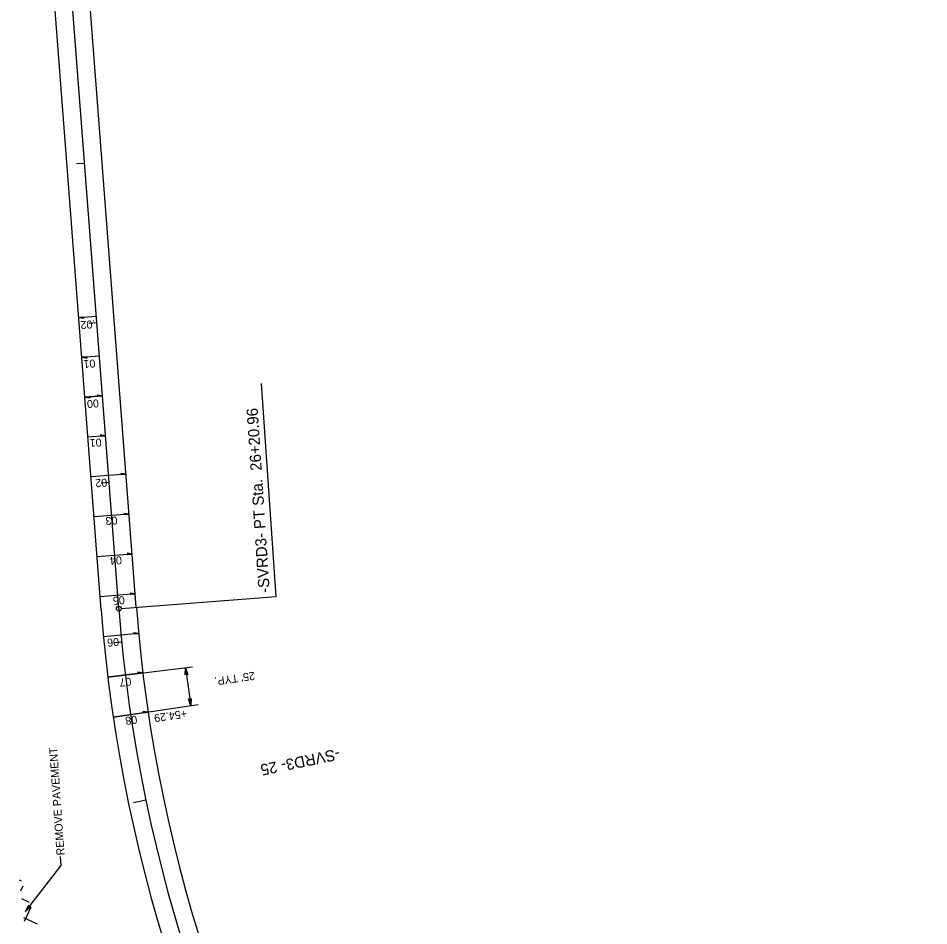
# Model space of a CAD drawing. Extents: x 2389694 to 2405615, y 547005 to 573532.
# Drawn here: x 2400508 to 2401078, y 564597 to 565164 of the extents above; entities that cross this region are included whole.
import ezdxf

# ---------------------------------------------------------------- set-up
doc = ezdxf.new("R2010")
doc.units = 0
for name, color, linetype in [('Prop Dimension', 7, 'Continuous'), ('Prop Dimension Text', 7, 'Continuous'), ('Prop EOT', 7, 'Continuous'), ('Prop Hatching', 7, 'Continuous'), ('Prop Horizontal Alignment', 7, 'Continuous'), ('Prop Horizontal Alignment Curve and Spiral Data', 7, 'Continuous'), ('Prop Horizontal Alignment Station Label', 7, 'Continuous'), ('Prop Horizontal Alignment Tick Label', 7, 'Continuous'), ('Prop Horizontal Alignment Tick Large', 7, 'Continuous'), ('Prop Horizontal Alignment Tick Small', 7, 'Continuous'), ('Prop Super Arrow 1 Lane CELL', 7, 'Continuous'), ('Prop Superelevation Label', 7, 'Continuous')]:
    doc.layers.add(name, color=color, linetype=linetype)

msp = doc.modelspace()

# ---------------------------------------------------------------- linework, layer by layer
at = {"layer": 'Prop Dimension'}
for p, q in [((2400564.55, 564752.49), (2400617.49, 564758.92)), ((2400613.05, 564758.38), (2400616.4, 564734.61)), ((2400567.92, 564727.43), (2400620.99, 564735.29))]:
    msp.add_line(p, q, dxfattribs=at)
for points in [[(2400612.91, 564753.81), (2400613.05, 564758.38), (2400614.47, 564754.01), (2400613.6, 564754.47)], [(2400616.54, 564739.17), (2400616.4, 564734.61), (2400614.97, 564738.98), (2400615.85, 564738.52)], [(2400516.37, 564609.1), (2400513, 564606.03), (2400515.14, 564610.09), (2400515.42, 564609.15)]]:
    msp.add_lwpolyline(points, close=True, dxfattribs=at)
msp.add_lwpolyline([(2400513, 564606.03), (2400535.32, 564634.75), (2400534.93, 564640.32)], dxfattribs=at)
at = {"layer": 'Prop EOT'}
for p, q in [((2400560.39, 564794.44), (2400416.1, 566667.86)), ((2400582.32, 564796.13), (2400442.32, 566613.9))]:
    msp.add_line(p, q, dxfattribs=at)
for radius in [961, 939]:
    msp.add_arc((2401518.55, 564868.23), radius, 184.40408, 241.98996, dxfattribs=at)
at = {"layer": 'Prop Hatching'}
for p, q in [((2400510.49, 564624.99), (2400509.31, 564625.54)), ((2400510.1, 564618.92), (2400511.58, 564622.09)), ((2400515.52, 564611.61), (2400510.7, 564613.86)), ((2400512.33, 564600.05), (2400516.5, 564608.99)), ((2400520.61, 564598.2), (2400512.08, 564602.18))]:
    msp.add_line(p, q, dxfattribs=at)
at = {"layer": 'Prop Horizontal Alignment'}
msp.add_line((2400571.36, 564795.28), (2400413.17, 566849.18), dxfattribs=at)
msp.add_arc((2401518.55, 564868.23), 950, 184.40408, 241.98996, dxfattribs=at)
at = {"layer": 'Prop Horizontal Alignment Curve and Spiral Data'}
msp.add_line((2400669.76, 564802.86), (2400660.46, 564935.91), dxfattribs=at)
at = {"layer": 'Prop Horizontal Alignment Station Label'}
msp.add_line((2400572.85, 564795.4), (2400669.76, 564802.86), dxfattribs=at)
msp.add_circle((2400571.36, 564795.28), 1.5, dxfattribs=at)
at = {"layer": 'Prop Horizontal Alignment Tick Large'}
msp.add_line((2400588.29, 564675.59), (2400580.45, 564673.97), dxfattribs=at)
at = {"layer": 'Prop Horizontal Alignment Tick Small'}
for p, q in [((2400549.93, 565073.49), (2400544.94, 565073.11)), ((2400557.61, 564973.79), (2400552.62, 564973.41)), ((2400565.29, 564874.09), (2400560.3, 564873.7)), ((2400573.2, 564774.4), (2400568.22, 564773.91))]:
    msp.add_line(p, q, dxfattribs=at)
at = {"layer": 'Prop Super Arrow 1 Lane CELL'}
for p, q in [((2400546.31, 564977.23), (2400557.28, 564978.07)), ((2400548.23, 564952.3), (2400559.2, 564953.14)), ((2400561.12, 564928.22), (2400550.15, 564927.37)), ((2400550.15, 564927.37), (2400561.12, 564928.22)), ((2400563.04, 564903.29), (2400552.07, 564902.45)), ((2400575.92, 564879.21), (2400553.99, 564877.52)), ((2400577.84, 564854.28), (2400555.91, 564852.59)), ((2400579.76, 564829.36), (2400557.83, 564827.67)), ((2400581.68, 564804.43), (2400559.75, 564802.74)), ((2400583.73, 564779.71), (2400561.83, 564777.64)), ((2400586.39, 564755.14), (2400564.55, 564752.49)), ((2400589.68, 564730.65), (2400567.92, 564727.43))]:
    msp.add_line(p, q, dxfattribs=at)
for points in [[(2400546.31, 564977.23), (2400549.57, 564976.74), (2400549.01, 564977.43)], [(2400548.23, 564952.3), (2400551.49, 564951.81), (2400550.93, 564952.51)], [(2400550.15, 564927.37), (2400553.41, 564926.89), (2400552.85, 564927.58)], [(2400561.12, 564928.22), (2400557.86, 564928.7), (2400558.42, 564928.01)], [(2400563.04, 564903.29), (2400559.78, 564903.78), (2400560.34, 564903.08)], [(2400575.92, 564879.21), (2400572.67, 564879.7), (2400573.23, 564879)], [(2400577.84, 564854.28), (2400574.59, 564854.77), (2400575.15, 564854.08)], [(2400579.76, 564829.36), (2400576.51, 564829.84), (2400577.07, 564829.15)], [(2400581.68, 564804.43), (2400578.43, 564804.92), (2400578.99, 564804.22)], [(2400583.73, 564779.71), (2400580.47, 564780.14), (2400581.04, 564779.45)], [(2400586.39, 564755.14), (2400583.11, 564755.48), (2400583.7, 564754.82)], [(2400589.68, 564730.65), (2400586.4, 564730.91), (2400587.01, 564730.26)]]:
    msp.add_lwpolyline(points, close=True, dxfattribs=at)

# ---------------------------------------------------------------- texts
at = {"layer": 'Prop Dimension Text'}
for s, rotation, p in [("25' TYP.", 188.3766, (2400656.01, 564755.86)), ('+54.29', 188.3766, (2400613.54, 564732.17)), ('REMOVE PAVEMENT', 94, (2400537.52, 564641.24))]:
    msp.add_text(s, height=5, rotation=rotation, dxfattribs=at).set_placement(p)
at = {"layer": 'Prop Horizontal Alignment Station Label'}
msp.add_text('-SVRD3- PT Sta.  26+20.96', height=7, rotation=93.7744, dxfattribs=at).set_placement((2400665.74, 564805.33))
at = {"layer": 'Prop Horizontal Alignment Tick Label'}
msp.add_text('-SVRD3- 25', height=7, rotation=191.6995, dxfattribs=at).set_placement((2400708.82, 564707.97))
at = {"layer": 'Prop Superelevation Label'}
for s, rotation, p in [('.02', 184.4041, (2400556.51, 564975.56)), ('01', 184.4041, (2400556.52, 564951.02)), ('00', 4.4041, (2400551.68, 564920.52)), ('01', 184.4041, (2400560.38, 564901.62)), ('02', 184.4041, (2400563.94, 564876.6)), ('03', 184.4041, (2400570.31, 564852.97)), ('04', 184.4041, (2400573.09, 564828.08)), ('05', 184.4041, (2400574.86, 564803.16)), ('06', 185.4094, (2400571.27, 564777.08)), ('07', 186.9172, (2400578.85, 564752.29)), ('08', 188.425, (2400582.47, 564728.54))]:
    msp.add_text(s, height=5, rotation=rotation, dxfattribs=at).set_placement(p)

doc.saveas('drawing.dxf')
